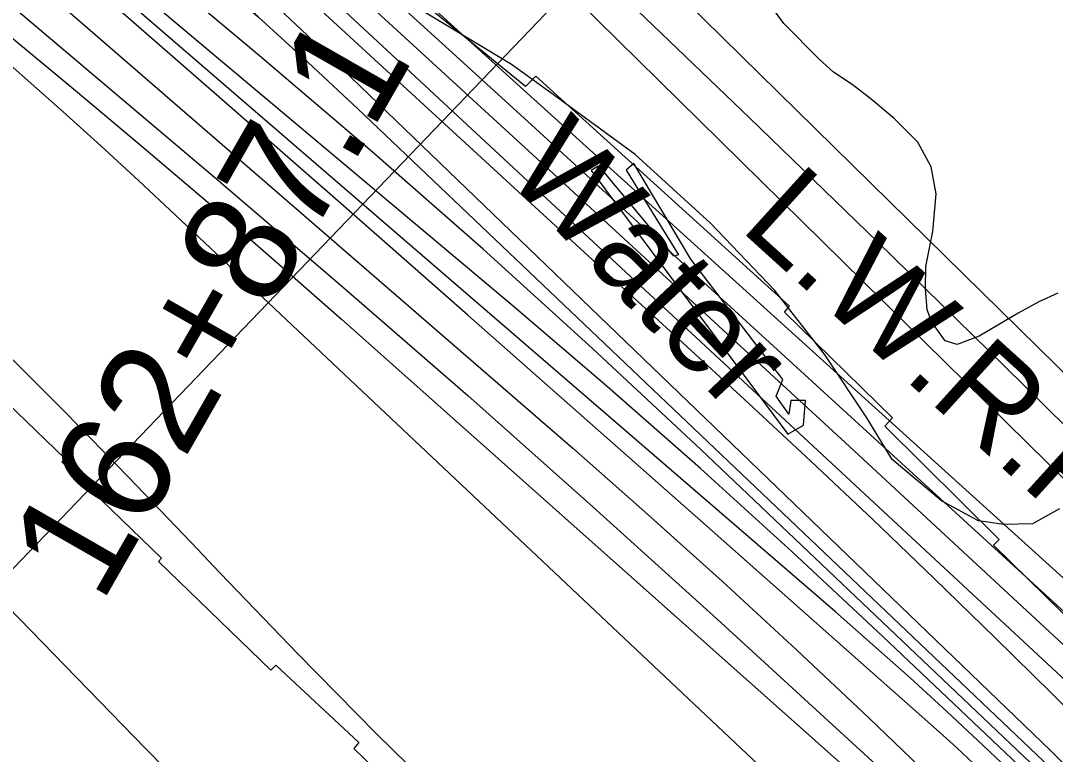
# Model space of a CAD drawing. Extents: x 3625074 to 3663148, y 511451 to 537151.
# Drawn here: x 3629186 to 3630111, y 533380 to 534036 of the extents above; entities that cross this region are included whole.
import ezdxf

# ---------------------------------------------------------------- set-up
doc = ezdxf.new("R2010")
doc.units = 0
for name, color, linetype in [('V-CHAN-DOCK', 7, 'Continuous'), ('V-RIVR-EDGE', 7, 'Continuous'), ('V-RIVR-IDEN', 7, 'Continuous'), ('V-RIVR-RANG', 7, 'Continuous'), ('V-RRAP-RVMT', 7, 'Continuous'), ('V-SITE-VEGE', 7, 'Continuous'), ('V-SURV-IDEN', 7, 'Continuous'), ('V-TOPO-DPTH', 7, 'Continuous'), ('V-TOPO-MAJR', 7, 'Continuous'), ('V-TOPO-MINR', 7, 'Continuous'), ('V-TOPO-WATR', 7, 'Continuous'), ('V-TOPO-WATR-IDEN', 7, 'Continuous')]:
    doc.layers.add(name, color=color, linetype=linetype)

msp = doc.modelspace()

# ---------------------------------------------------------------- linework, layer by layer
at = {"layer": 'V-CHAN-DOCK'}
msp.add_lwpolyline([(3629702.38, 533905.84), (3629696.41, 533901.78), (3629872, 533666.23), (3629885.93, 533674.38), (3629887.71, 533696.43), (3629874.7, 533696.3), (3629872.82, 533684.27), (3629861.64, 533700.17), (3629867.5, 533715.25), (3629785.32, 533822.57), (3629734.39, 533908.16), (3629727.45, 533902.09), (3629774.26, 533826.46), (3629770.27, 533825.42), (3629703.38, 533905.85), (3629703.38, 533905.85)], dxfattribs=at)
at = {"layer": 'V-RIVR-EDGE'}
msp.add_lwpolyline([(3630114.73, 533599.69), (3630090.8, 533586.27), (3630065.07, 533585.72), (3630042.41, 533588.84), (3630009.36, 533606.69), (3629965.34, 533643.56), (3629942.76, 533680.99), (3629905.52, 533736.84), (3629860.32, 533794.55), (3629802.87, 533854.74), (3629735.63, 533916.18), (3629663.45, 533969.05), (3629624.92, 533996.72), (3629527.03, 534055.78)], dxfattribs=at)
at = {"layer": 'V-RIVR-RANG'}
msp.add_line((3629988.66, 534389.01), (3629144.15, 533509.33), dxfattribs=at)
at = {"layer": 'V-RRAP-RVMT'}
for p, q in [((3629637.48, 533976.92), (3629521.98, 534071.12)), ((3629646.81, 533986.27), (3629637.48, 533976.92)), ((3629873.62, 533780.61), (3629646.81, 533986.27)), ((3629868.93, 533775.46), (3629873.62, 533780.61)), ((3629965.58, 533680.83), (3629868.93, 533775.46)), ((3629142.08, 533725.27), (3629225.76, 533644.48)), ((3629958.81, 533673.56), (3629965.58, 533680.83)), ((3630060.87, 533572.23), (3629958.81, 533673.56)), ((3629225.76, 533644.48), (3629223.11, 533641.61)), ((3629223.11, 533641.61), (3629312.23, 533555.55)), ((3630055.85, 533567.15), (3630060.87, 533572.23)), ((3630156.4, 533468.42), (3630055.85, 533567.15)), ((3629312.23, 533555.55), (3629309.5, 533552.62)), ((3629309.5, 533552.62), (3629410.12, 533455.46)), ((3629410.12, 533455.46), (3629414.39, 533459.89)), ((3629414.39, 533459.89), (3629488.77, 533390.83)), ((3629488.77, 533390.83), (3629484.05, 533385.47)), ((3629484.05, 533385.47), (3629587.66, 533286.77))]:
    msp.add_line(p, q, dxfattribs=at)
at = {"layer": 'V-SITE-VEGE'}
msp.add_lwpolyline([(3630113.24, 533792.18), (3630096.38, 533784.63), (3630077.76, 533774.39), (3630043.16, 533753.99), (3630023.46, 533746.57), (3630012.61, 533749.74), (3630000.81, 533766.29), (3629996.45, 533777.34), (3629995.14, 533796.4), (3629995.44, 533816.11), (3630001.53, 533847.34), (3630004.5, 533881.13), (3630000.21, 533905.18), (3629988.06, 533927.2), (3629967, 533948.38), (3629946.44, 533965.71), (3629929.65, 533978.67), (3629912.91, 533989.61), (3629900.01, 534001.45), (3629868.31, 534033.32), (3629860.3, 534044.28)], dxfattribs=at)
at = {"layer": 'V-TOPO-DPTH'}
for points in [[(3629135.05, 534458.04), (3629133.68, 534600.4), (3629167.83, 534570.76), (3629347.52, 534414.04), (3629358.37, 534404.46), (3629369.14, 534394.79), (3629379.79, 534384.99), (3629390.35, 534375.1), (3629607.87, 534169.02), (3629723.07, 534059.27), (3629837.86, 533949.08), (3629952.03, 533838.25), (3630065.78, 533726.99), (3630250.23, 533545.56), (3630271.34, 533524.58), (3630292.3, 533503.46), (3630313.03, 533482.12), (3630333.62, 533460.63), (3630452.97, 533334.79), (3630491.75, 533291.77), (3630529.03, 533247.54), (3630564.04, 533201.5), (3630597.54, 533154.25), (3630641.65, 533088.6)], [(3629135.05, 534458.04), (3629242.49, 534333.52), (3629245.95, 534329.58), (3629249.46, 534325.68), (3629253.04, 534321.84), (3629256.67, 534318.05), (3629260.36, 534314.32), (3629264.1, 534310.63), (3629267.9, 534307.01), (3629271.74, 534303.44), (3629283.53, 534292.68), (3629285.33, 534291.03), (3629288.95, 534287.74), (3629290.77, 534286.1), (3629318.29, 534261.24), (3629333.86, 534247.17), (3629349.43, 534233.1), (3629365, 534219.03), (3629380.57, 534204.95), (3630177.33, 533484.27)], [(3630177.33, 533484.27), (3629380.57, 534204.95), (3629365, 534219.03), (3629349.43, 534233.1), (3629333.86, 534247.17), (3629318.29, 534261.24), (3629290.77, 534286.1), (3629288.95, 534287.74), (3629285.33, 534291.03), (3629283.53, 534292.68), (3629271.74, 534303.44), (3629267.9, 534307.01), (3629264.1, 534310.63), (3629260.36, 534314.32), (3629256.67, 534318.05), (3629253.04, 534321.84), (3629249.46, 534325.68), (3629245.95, 534329.58), (3629242.49, 534333.52), (3629135.05, 534458.04)], [(3629135.78, 534381.99), (3629155.61, 534363.66), (3629221.13, 534303.82), (3629243.7, 534283.19), (3629266.26, 534262.55), (3629288.8, 534241.89), (3629311.33, 534221.23), (3629658.33, 533902.65), (3629748, 533820.24), (3629837.6, 533737.76), (3629927.1, 533655.17), (3630016.54, 533572.51), (3630178.96, 533422.24), (3630187.05, 533414.58), (3630195.02, 533406.79), (3630202.81, 533398.83), (3630210.48, 533390.75), (3630237.19, 533361.95)], [(3630237.19, 533361.95), (3630210.48, 533390.75), (3630202.81, 533398.83), (3630195.02, 533406.79), (3630187.05, 533414.58), (3630178.96, 533422.24), (3630016.54, 533572.51), (3629927.1, 533655.17), (3629837.6, 533737.76), (3629748, 533820.24), (3629658.33, 533902.65), (3629311.33, 534221.23), (3629288.8, 534241.89), (3629266.26, 534262.55), (3629243.7, 534283.19), (3629221.13, 534303.82), (3629155.61, 534363.66), (3629135.78, 534381.99)], [(3630646.78, 532833.24), (3630380.24, 533142.58), (3630345.3, 533182.61), (3630310.03, 533222.34), (3630274.26, 533261.63), (3630238.16, 533300.61), (3630220.68, 533319.25), (3630192.89, 533348.52), (3630164.87, 533377.56), (3630136.49, 533406.25), (3630107.88, 533434.72), (3630057.22, 533484.52), (3630002.85, 533537.43), (3629948.12, 533589.98), (3629892.87, 533641.98), (3629837.27, 533693.62), (3629267.41, 534217.54), (3629256.86, 534227.22), (3629246.29, 534236.9), (3629235.71, 534246.55), (3629225.11, 534256.18), (3629136.21, 534336.87)], [(3630646.78, 532833.24), (3630380.24, 533142.58), (3630345.3, 533182.61), (3630310.03, 533222.34), (3630274.26, 533261.63), (3630238.16, 533300.61), (3630220.68, 533319.25), (3630192.89, 533348.52), (3630164.87, 533377.56), (3630136.49, 533406.25), (3630107.88, 533434.72), (3630057.22, 533484.52), (3630002.85, 533537.43), (3629948.12, 533589.98), (3629892.87, 533641.98), (3629837.27, 533693.62), (3629267.41, 534217.54), (3629256.86, 534227.22), (3629246.29, 534236.9), (3629235.71, 534246.55), (3629225.11, 534256.18), (3629136.21, 534336.87)], [(3629136.56, 534299.79), (3629228.3, 534218.87), (3629231.82, 534215.75), (3629232.99, 534214.7), (3629302.02, 534152.95), (3629337.53, 534120.84), (3629372.8, 534088.47), (3629407.72, 534055.73), (3629442.41, 534022.72), (3630107.02, 533383.42), (3630122.7, 533368.02), (3630138.17, 533352.4), (3630153.31, 533336.47), (3630168.23, 533320.32), (3630633.29, 532806.55), (3630635.83, 532803.68), (3630637.07, 532802.21), (3630639.71, 532799.01), (3630642.78, 532795.34)], [(3629136.56, 534299.79), (3629228.3, 534218.87), (3629231.82, 534215.75), (3629232.99, 534214.7), (3629302.02, 534152.95), (3629337.53, 534120.84), (3629372.8, 534088.47), (3629407.72, 534055.73), (3629442.41, 534022.72), (3630107.02, 533383.42), (3630122.7, 533368.02), (3630138.17, 533352.4), (3630153.31, 533336.47), (3630168.23, 533320.32), (3630633.29, 532806.55), (3630635.83, 532803.68), (3630637.07, 532802.21), (3630639.71, 532799.01), (3630642.78, 532795.34)], [(3630106.81, 533368.17), (3629487.61, 533957.08), (3629443.4, 533998.37), (3629398.69, 534039.11), (3629353.25, 534079.03), (3629307.32, 534118.4), (3629273.78, 534146.62), (3629244.14, 534171.33), (3629214.36, 534195.87), (3629184.36, 534220.14), (3629154.21, 534244.23), (3629136.97, 534257.89)], [(3629136.97, 534257.89), (3629154.21, 534244.23), (3629184.36, 534220.14), (3629214.36, 534195.87), (3629244.14, 534171.33), (3629273.78, 534146.62), (3629307.32, 534118.4), (3629353.25, 534079.03), (3629398.69, 534039.11), (3629443.4, 533998.37), (3629487.61, 533957.08), (3630106.81, 533368.17)]]:
    msp.add_lwpolyline(points, dxfattribs=at)
at = {"layer": 'V-TOPO-MAJR'}
for points in [[(3630106.77, 533355.86), (3629794.18, 533652.73), (3629697.55, 533742.79), (3629599.82, 533831.62), (3629500.45, 533918.61), (3629399.97, 534004.36), (3629234.9, 534142.6), (3629216.07, 534158.22), (3629197.13, 534173.72), (3629178.03, 534189.02), (3629158.84, 534204.21), (3629137.32, 534221.06)], [(3629138.65, 534082.3), (3629146.84, 534075.59), (3629162.66, 534062.4), (3629359.58, 533896.02), (3629473.19, 533798.88), (3629586.02, 533700.84), (3629697.67, 533601.48), (3629808.55, 533501.22), (3630036.2, 533292.91)]]:
    msp.add_lwpolyline(points, dxfattribs=at)
at = {"layer": 'V-TOPO-MINR'}
for points in [[(3630783.38, 533068.08), (3630356.88, 533487.49), (3630336.61, 533507.42), (3630316.34, 533527.34), (3630296.06, 533547.25), (3630275.77, 533567.16), (3630255.49, 533587.07), (3630235.21, 533606.98), (3630214.93, 533626.89), (3630194.65, 533646.8), (3629449.42, 534378.69), (3629422.98, 534404.36), (3629396.35, 534429.83), (3629369.44, 534455.01), (3629342.34, 534479.98), (3629333.88, 534487.68), (3629302.37, 534516.32), (3629270.82, 534544.91), (3629239.21, 534573.43), (3629207.55, 534601.9), (3629177.01, 534629.3), (3629136.89, 534667.01), (3629133, 534670.89)], [(3630641.65, 533088.6), (3630597.54, 533154.25), (3630564.04, 533201.5), (3630529.03, 533247.54), (3630491.75, 533291.77), (3630452.97, 533334.79), (3630333.62, 533460.63), (3630313.03, 533482.12), (3630292.3, 533503.46), (3630271.34, 533524.58), (3630250.23, 533545.56), (3630065.78, 533726.99), (3629952.03, 533838.25), (3629837.86, 533949.08), (3629723.07, 534059.27), (3629607.87, 534169.02), (3629390.35, 534375.1), (3629379.79, 534384.99), (3629369.14, 534394.79), (3629358.37, 534404.46), (3629347.52, 534414.04), (3629167.83, 534570.76), (3629133.68, 534600.4)], [(3630365.56, 533373.57), (3630342.74, 533399.52), (3630319.38, 533425.02), (3630285.07, 533461.32), (3630276.51, 533470.29), (3630267.88, 533479.19), (3630259.15, 533488), (3630250.36, 533496.75), (3629464.22, 534270.33), (3629446.07, 534288.04), (3629427.81, 534305.63), (3629409.39, 534323.06), (3629390.86, 534340.38), (3629356.17, 534372.53), (3629354.9, 534373.68), (3629352.33, 534375.93), (3629351.02, 534377.03), (3629134.11, 534555.13)], [(3630295.69, 533332.11), (3630241.9, 533390.11), (3630226.43, 533406.37), (3630210.71, 533422.38), (3630194.59, 533437.98), (3630178.21, 533453.33), (3629720.29, 533871.83), (3629646.44, 533939.28), (3629572.56, 534006.69), (3629498.63, 534074.05), (3629424.67, 534141.38), (3629292.89, 534261.27), (3629284.8, 534268.63), (3629276.72, 534275.99), (3629268.64, 534283.36), (3629260.56, 534290.73), (3629210.84, 534336.14), (3629192.15, 534353.46), (3629173.64, 534370.96), (3629155.38, 534388.73), (3629137.3, 534406.68), (3629135.52, 534408.49)], [(3630237.19, 533361.95), (3630210.48, 533390.75), (3630202.81, 533398.83), (3630195.02, 533406.79), (3630187.05, 533414.58), (3630178.96, 533422.24), (3630016.54, 533572.51), (3629927.1, 533655.17), (3629837.6, 533737.76), (3629748, 533820.24), (3629658.33, 533902.65), (3629311.33, 534221.23), (3629288.8, 534241.89), (3629266.26, 534262.55), (3629243.7, 534283.19), (3629221.13, 534303.82), (3629155.61, 534363.66), (3629135.78, 534381.99)], [(3631278.63, 532107.69), (3630700.39, 532792.34), (3630687.16, 532807.93), (3630673.88, 532823.49), (3630660.53, 532838.98), (3630647.13, 532854.43), (3630182.1, 533388.18), (3630181.65, 533388.7), (3630179.78, 533390.7), (3630177.19, 533393.29), (3630175.76, 533394.67), (3630175.03, 533395.35), (3629288.24, 534219.12), (3629272.03, 534234.14), (3629255.8, 534249.12), (3629239.53, 534264.07), (3629223.24, 534278.99), (3629136, 534358.66)], [(3630646.78, 532833.24), (3630380.24, 533142.58), (3630345.3, 533182.61), (3630310.03, 533222.34), (3630274.26, 533261.63), (3630238.16, 533300.61), (3630220.68, 533319.25), (3630192.89, 533348.52), (3630164.87, 533377.56), (3630136.49, 533406.25), (3630107.88, 533434.72), (3630057.22, 533484.52), (3630002.85, 533537.43), (3629948.12, 533589.98), (3629892.87, 533641.98), (3629837.27, 533693.62), (3629267.41, 534217.54), (3629256.86, 534227.22), (3629246.29, 534236.9), (3629235.71, 534246.55), (3629225.11, 534256.18), (3629136.21, 534336.87)], [(3630106.81, 533368.17), (3629487.61, 533957.08), (3629443.4, 533998.37), (3629398.69, 534039.11), (3629353.25, 534079.03), (3629307.32, 534118.4), (3629273.78, 534146.62), (3629244.14, 534171.33), (3629214.36, 534195.87), (3629184.36, 534220.14), (3629154.21, 534244.23), (3629136.97, 534257.89)], [(3630106.74, 533343.57), (3629956.98, 533485.6), (3629875.93, 533561.08), (3629794, 533635.56), (3629710.74, 533708.56), (3629626.58, 533780.55), (3629200.05, 534138.86), (3629190.91, 534146.42), (3629181.69, 534153.88), (3629172.36, 534161.19), (3629162.95, 534168.4), (3629137.64, 534187.49)], [(3630106.72, 533331.28), (3630046.6, 533388.22), (3630014.08, 533418.59), (3629981.28, 533448.66), (3629948.07, 533478.26), (3629914.57, 533507.56), (3629184.6, 534137.12), (3629179.79, 534141.18), (3629174.93, 534145.19), (3629170, 534149.1), (3629165.01, 534152.95), (3629137.78, 534173.56)], [(3630038.19, 533371.92), (3630022.97, 533386.21), (3630007.5, 533400.24), (3629793.88, 533589.27), (3629690.03, 533680.99), (3629586.07, 533772.58), (3629481.94, 533863.98), (3629377.69, 533955.25), (3629171.12, 534135.76), (3629170.06, 534136.67), (3629166.81, 534139.27), (3629137.9, 534161.16)], [(3629138.28, 534121.29), (3629149.33, 534112.33), (3629176.81, 534089.36), (3629204.06, 534066.1), (3629679.79, 533653.82), (3629747.05, 533594.65), (3629813.71, 533534.81), (3629879.47, 533473.98), (3629944.62, 533412.5), (3630035.97, 533324.99)], [(3629138.93, 534053.24), (3629237.15, 533971.79), (3629296.79, 533921.79), (3629356.09, 533871.39), (3629414.86, 533820.38), (3629473.27, 533768.95), (3630036.94, 533267.49)], [(3629139.16, 534029.56), (3629190.3, 533984.53), (3629224.3, 533954.28), (3629258.09, 533923.8), (3629291.57, 533892.99), (3629324.84, 533861.94), (3629965.67, 533257.97)], [(3629575.74, 533328.92), (3629504.23, 533398.88), (3629433.99, 533470.11), (3629364.58, 533542.19), (3629339.13, 533569.11), (3629282.72, 533627.99), (3629225.81, 533686.4), (3629168.18, 533744.08), (3629141.65, 533770.18)], [(3630401.51, 532263.41), (3630310.9, 532359), (3630291.29, 532379.67), (3630271.64, 532400.31), (3630251.97, 532420.92), (3630232.27, 532441.5), (3630179.09, 532496.98), (3630132.67, 532545.18), (3630086.08, 532593.21), (3630039.26, 532641.02), (3629992.27, 532688.66), (3629785.2, 532897.59), (3629759.7, 532923.24), (3629734.15, 532948.83), (3629708.52, 532974.35), (3629682.85, 532999.82), (3629587.99, 533093.62), (3629515.04, 533166.15), (3629442.35, 533238.93), (3629370.05, 533312.1), (3629298.01, 533385.53), (3629143.82, 533543.53)]]:
    msp.add_lwpolyline(points, dxfattribs=at)
at = {"layer": 'V-TOPO-WATR'}
msp.add_lwpolyline([(3630177.33, 533484.27), (3629380.57, 534204.95), (3629365, 534219.03), (3629349.43, 534233.1), (3629333.86, 534247.17), (3629318.29, 534261.24), (3629290.77, 534286.1), (3629288.95, 534287.74), (3629285.33, 534291.03), (3629283.53, 534292.68), (3629271.74, 534303.44), (3629267.9, 534307.01), (3629264.1, 534310.63), (3629260.36, 534314.32), (3629256.67, 534318.05), (3629253.04, 534321.84), (3629249.46, 534325.68), (3629245.95, 534329.58), (3629242.49, 534333.52), (3629135.05, 534458.04)], dxfattribs=at)

# ---------------------------------------------------------------- texts
at = {"layer": 'V-RIVR-IDEN'}
msp.add_text('Water', height=83, rotation=313.38109, dxfattribs=at).set_placement((3629617.58, 533898.64))
at = {"layer": 'V-SURV-IDEN'}
msp.add_text('162+87.1', height=100, rotation=60.22229, dxfattribs=at).set_placement((3629258.37, 533513.64))
at = {"layer": 'V-TOPO-WATR-IDEN'}
msp.add_text('L.W.R.P.', height=83, rotation=317.77501, dxfattribs=at).set_placement((3629827.94, 533849.82))

doc.saveas('drawing.dxf')
